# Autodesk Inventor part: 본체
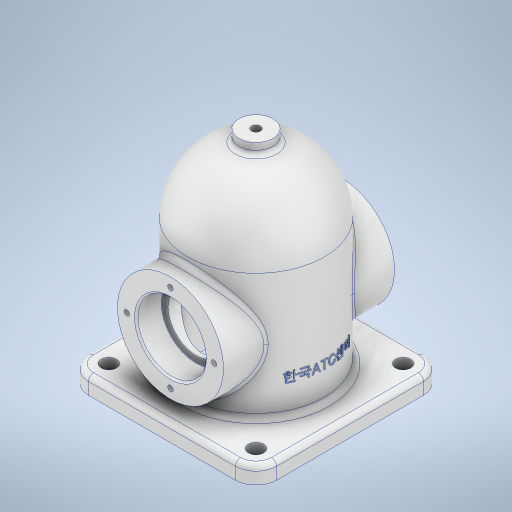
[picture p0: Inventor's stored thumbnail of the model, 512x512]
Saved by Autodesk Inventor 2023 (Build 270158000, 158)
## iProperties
Created: 2025-04
Part Number: 본체
Material: 알루미늄 6061
Document SubType Name: Modeling
Designer: ADMIN_PC
Density: 2.7 g/cm^3
Appearance: 알루미늄 - 평지
Mass: 865.906 g
Surface Area: 800.755 cm^2
Volume: 320.706 cm^3
Author: ADMIN_PC
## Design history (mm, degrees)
node "작업 평면1"
sketch "스케치1"
  geometry: L1 (-55, 55)-(55, 55); L2 (55, 55)-(55, -55); L3 (55, -55)-(-55, -55); L4 (-55, -55)-(-55, 55); L5 (-55, 55)-(55, -55); L6 (55, 55)-(-55, -55); 1 further point
  constraints: 12 end point, 2 midpoint, 2 parallel, 1 horizontal, 1 perpendicular
  dimensions: "d1" = 110 distance of L2.end L3.end; "d2" = 110 distance of L1.end L2.end
extrude "돌출1" new body sketch "스케치1" distance "d3" = 10; taper "d4" = 0 deg
sketch "스케치2"
  geometry: C1 r 40 at (0, 0); 1 further point
  constraints: 1 centre point, 1 coincident
  dimensions: "d5" = 80 diameter of C1
extrude "돌출2" join sketch "스케치2" distance "d6" = 74; taper "d7" = 0 deg
sketch "스케치3"
  geometry: L1 (36, -40)-(36, 40) reference; L2 (76, 0)-(36, 0); L3 (-74.457, 0)-(110.741, 0) reference; A1 r 40 centre (36, 0) between (76, 0) and (36, 40); 1 further point
  constraints: 2 end point, 2 point on circle, 1 centre point, 1 horizontal, 1 midpoint
revolve "회전1" sketch "스케치3" stored, may be unused: angle "d8" = 90 deg
sketch "스케치4"
  geometry: C1 r 10 at (0, 0); 1 further point
  constraints: 1 centre point, 1 coincident
  dimensions: "d9" = 20 diameter of C1
extrude "돌출3" join sketch "스케치4" distance "d10" = 129; taper "d11" = 0 deg
sketch "스케치5"
  geometry: L1 (36, -40)-(36, 40) reference; L2 (-73.8, 0)-(106.8, 0) reference; L3 (36, 32)-(-48, 32); L4 (-48, -55)-(-48, 55) reference; L5 (-48, 32)-(-48, 0); L6 (68, 0)-(-48, 0); A1 r 32 centre (36, 0) between (68, 0) and (36, 32); 2 further points
  constraints: 6 end point, 4 point on line, 2 midpoint, 2 point on circle, 1 centre point, 1 horizontal, 1 perpendicular
  dimensions: "d12" = 32 radius of A1
sketch "스케치6"
  geometry: L1 (55, -48)-(-55, -48) reference; L2 (0, -48)-(0, 0); C1 r 31 at (0, 0)
  constraints: 2 end point, 1 centre point, 1 coincident, 1 midpoint, 1 vertical
  dimensions: "d13" = 48 distance of L2.start L2.end (derived); "d14" = 62 diameter of C1
extrude "돌출4" join sketch "스케치6" stored distance "d15" = 100; taper "d16" = 0 deg
revolve "회전2" stored, may be unused: angle "d17" = 90 deg
sketch "스케치7"
  geometry: C1 r 16.5 at (0, 0); 1 further point
  constraints: 1 centre point, 1 coincident
  dimensions: "d18" = 33 diameter of C1
extrude "돌출5" cut sketch "스케치7" extent not by distance; stored distance "d19" = 0; taper "d20" = 0 deg
sketch "스케치8"
  geometry: C1 r 16.5 at (0, 0) reference; C2 r 20 at (0, 0); 1 further point
  constraints: 1 centre point, 1 coincident
  dimensions: "d21" = 40 diameter of C2
extrude "돌출6" cut sketch "스케치8" distance "d22" = 15; taper "d23" = 0 deg
sketch "스케치9" dims "d24" = 51
  geometry: L1 (0, -73.8)-(0, 106.8) reference; 3 further points
  constraints: 1 coincident, 1 point on line, 1 vertical alignment, 2 other
hole "구멍1" sketch "스케치9" at (0, 25.5) diameter "d25" = 3.242; stored, may be unused: countersink angle "d29" = 90 deg, drill point angle "d31" = 118 deg; dims "d26" = 8, "d27" = 4, "d28" = 2, "d30" = 10
sketch "스케치10"
  geometry: 2 further points
  constraints: 1 coincident
hole "구멍2" sketch "스케치10" at (0, 0) diameter "d35" = 5.1881; stored, may be unused: countersink angle "d39" = 90 deg, drill point angle "d41" = 118 deg; dims "d36" = 20, "d37" = 4, "d38" = 2, "d40" = 21
fillet "모깎기1" dims "d42" = 12
sketch "스케치11"
  geometry: C1 r 4.5 at (-43, -43); C2 r 4.5 at (-43, 43); C3 r 4.5 at (43, -43); C4 r 4.5 at (43, 43); A1 r 12 centre (-43, -43) between (-55, -43) and (-43, -55) reference; A2 r 12 centre (-43, 43) between (-43, 55) and (-55, 43) reference; A3 r 12 centre (43, -43) between (43, -55) and (55, -43) reference; A4 r 12 centre (43, 43) between (55, 43) and (43, 55) reference; 1 further point
  constraints: 4 centre point, 4 coincident
  dimensions: "d43" = 9 diameter of C1; "d44" = 9 diameter of C2; "d45" = 9 diameter of C3; "d46" = 9 diameter of C4
extrude "돌출7" cut sketch "스케치11" extent not by distance; stored distance "d47" = 0; taper "d48" = 0 deg
node "작업 평면2"
sketch "스케치12"
  geometry: L1 (-48, -43)-(-48, 43) reference; L2 (-48, 0)-(-18, 0); 2 further points
  constraints: 2 end point, 1 coincident, 1 horizontal, 1 midpoint, 1 other
  dimensions: "d50" = 30 distance of L2.start L2.end
feature "엠보싱1" sketch "스케치12" dims "d1" = 110, "d2" = 110, "d9" = 20, "d51" = 0.5, "d52" = 0
fillet "모깎기2" dims "d53" = 0.3
fillet "모깎기3" dims "d54" = 3
chamfer "모따기1" distance "d55" = 1; stored, may be unused: second distance "d56" = 2, angle "d57" = 45 deg
feature "̤耀̦耀̨耀̪耀̬耀̮耀̰耀̲耀" dims "d0" = -48, "d1" = 110, "d2" = 110, "d3" = 10, "d4" = 0, "d5" = 80, "d6" = 74, "d7" = 0, "d8" = 90 deg, "d9" = 20, "d10" = 129, "d11" = 0, "d12" = 32, "d13" = 48 (derived), "d14" = 62, "d15" = 100, "d16" = 0, "d17" = 90 deg, "d18" = 33, "d19" = 0, "d20" = 0, "d21" = 40, "d22" = 15, "d23" = 0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
node "솔리드1"
mirror "미러1"
pattern_circular "원형 패턴1" dims angle "d33" = 360 deg
mirror "미러2"
feature "A9D066F2-1C7D-4E18-AEED-F7BC21143FA4" dims "d25" = 3.242, "d26" = 8, "d27" = 4, "d28" = 2, "d29" = 90 deg, "d30" = 10, "d31" = 118 deg
